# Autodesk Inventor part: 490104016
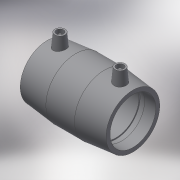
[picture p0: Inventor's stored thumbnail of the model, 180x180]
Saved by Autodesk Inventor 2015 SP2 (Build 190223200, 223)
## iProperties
Created: 2017-06
Part Number: 490104016
Material: Generic
Description: PLASSON COUPLER 16-16
Document SubType Name: Modeling
Designer: KIM
Mass: 56.9068 g
Surface Area: 157.941 cm^2
Volume: 56.9068 cm^3
Density: 1 g/cm^3
Appearance: Default
Author: KIM
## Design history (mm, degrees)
derived "490104.ipt"
feature "Solid1::490104.ipt"
tag "TaggingFeature1"
body "Solid1"
other parameters: "d0" = 71, "d1" = 16, "d2" = 35, "d3" = 34, "d4" = 23.66667, "d5" = 31.5, "d6" = 15.2, "d7" = 16, "d8" = 168 deg, "d10" = 13.6, "d11" = 4.53333, "d13" = 71, "d14" = 17.6296, "d15" = 34, "d16" = 34, "d17" = 15.2, "d18" = 16, "d19" = 3.52592, "d20" = 168 deg, "d22" = 32.9, "d23" = 35, "d24" = 31.913, "d25" = 135 deg, "d26" = 28.4, "d27" = 135 deg, "d29" = 39, "d30" = 14, "d31" = 24.85, "d34" = 5 deg, "d35" = 15, "d39" = 5 deg, "d41" = 4, "d42" = 14, "d43" = 0, "d45" = 4, "d46" = 14, "d47" = 0, "d48" = 3, "d49" = 0, "d50" = 3, "d51" = 0, "d52" = 9.86, "d53" = 2.465, "d_" = 16, "L_" = 71, "L_1" = 34, "D_" = 35, "A_" = 39, "d_2" = 12
